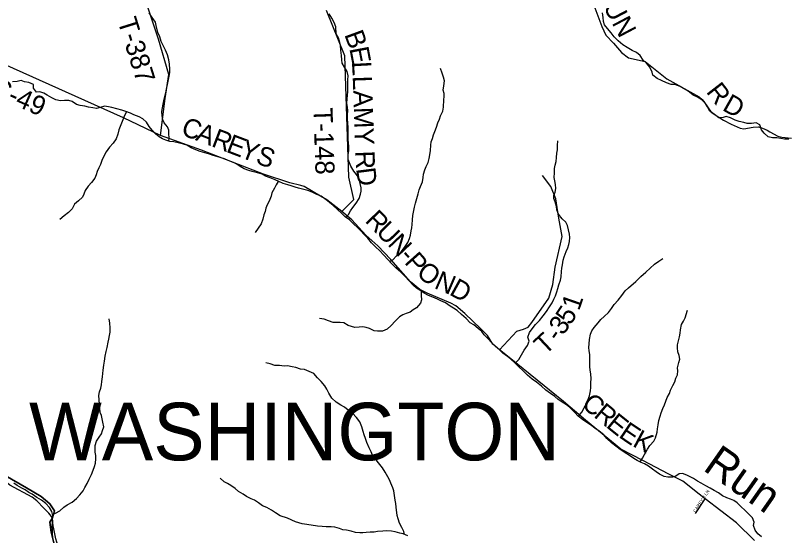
# Model space of a CAD drawing. Extents: x 1624196 to 2029251, y 146837 to 440034.
# Drawn here: x 1799187 to 1811228, y 265741 to 273872 of the extents above; entities that cross this region are included whole.
import ezdxf

# ---------------------------------------------------------------- set-up
doc = ezdxf.new("R2010")
doc.units = 0
for name, color, linetype in [('GM_X_County_Road', 7, 'Continuous'), ('GM_X_County_Road_Text', 7, 'Continuous'), ('GM_X_Minor_River', 7, 'Continuous'), ('GM_X_Minor_River_Text', 7, 'Continuous'), ('GM_X_Township', 7, 'Continuous'), ('GM_X_Township_Road', 7, 'Continuous'), ('GM_X_Township_Road_Text', 7, 'Continuous'), ('GM_X_Township_Subdivision', 7, 'Continuous'), ('GM_X_Township_Subdivision_Text', 7, 'Continuous'), ('GM_X_Township_Text', 7, 'Continuous')]:
    doc.layers.add(name, color=color, linetype=linetype)

msp = doc.modelspace()

# ---------------------------------------------------------------- linework, layer by layer
at = {"layer": 'GM_X_County_Road'}
for points in [[(1808218, 274031), (1808342, 273699), (1808404, 273563), (1808527, 273438), (1808649, 273294), (1808758, 273207), (1809022, 273150), (1809359, 272882), (1809863, 272597), (1809912, 272559), (1809937, 272527), (1810051, 272359), (1810095, 272327), (1810245, 272233), (1810364, 272171), (1810503, 272109), (1810563, 272100), (1810707, 272127), (1810790, 272129), (1810850, 272111), (1810927, 272077), (1810966, 272053), (1811094, 271982), (1811154, 271969), (1811305, 271951)], [(1810726, 265663), (1810447, 265938), (1809959, 266317), (1809862, 266391), (1809607, 266593), (1809390, 266700), (1808982, 266917), (1808639, 267094), (1808086, 267546), (1807745, 267836), (1806922, 268503), (1806743, 268646), (1806642, 268732), (1806557, 268868), (1806453, 268975), (1806202, 269214), (1806062, 269332), (1805984, 269374), (1805617, 269531), (1805504, 269585), (1805357, 269706), (1805047, 270059), (1804845, 270269), (1804661, 270436), (1804441, 270674), (1804283, 270805), (1804050, 270987), (1803949, 271048), (1803698, 271196), (1803646, 271212), (1803471, 271257), (1803060, 271390), (1802091, 271764), (1801451, 271994), (1800873, 272273), (1800121, 272608), (1798898, 273159)]]:
    msp.add_lwpolyline(points, dxfattribs=at)
at = {"layer": 'GM_X_Minor_River'}
for points in [[(1801383, 273713), (1801375, 273768), (1801321, 273840), (1801274, 273913)], [(1804189, 273695), (1804165, 273759), (1804129, 273831), (1804084, 273898)], [(1808432, 273668), (1808384, 273722), (1808368, 273776), (1808362, 273838), (1808353, 273911)], [(1801584, 271906), (1801587, 271957), (1801585, 272023), (1801580, 272077), (1801562, 272131), (1801512, 272192), (1801489, 272242), (1801477, 272300), (1801474, 272369), (1801484, 272429), (1801494, 272485), (1801505, 272535), (1801521, 272605), (1801534, 272661), (1801546, 272721), (1801560, 272790), (1801575, 272872), (1801587, 272922), (1801596, 272978), (1801596, 273034), (1801593, 273111), (1801583, 273177), (1801560, 273257), (1801532, 273328), (1801496, 273404), (1801465, 273465), (1801443, 273535), (1801412, 273607), (1801383, 273713)], [(1804347, 270713), (1804390, 270759), (1804420, 270815), (1804455, 270867), (1804509, 270937), (1804552, 271009), (1804574, 271077), (1804584, 271127), (1804585, 271179), (1804571, 271247), (1804561, 271298), (1804530, 271366), (1804472, 271437), (1804425, 271513), (1804403, 271568), (1804385, 271622), (1804382, 271692), (1804392, 271754), (1804393, 271827), (1804389, 271877), (1804384, 271939), (1804380, 272011), (1804380, 272065), (1804383, 272128), (1804379, 272184), (1804374, 272260), (1804374, 272310), (1804376, 272387), (1804371, 272439), (1804363, 272501), (1804366, 272561), (1804372, 272623), (1804376, 272678), (1804377, 272730), (1804375, 272798), (1804378, 272866), (1804382, 272928), (1804366, 272993), (1804325, 273065), (1804291, 273126), (1804286, 273176), (1804280, 273246), (1804269, 273331), (1804261, 273401), (1804251, 273451), (1804234, 273519), (1804194, 273586), (1804189, 273695)], [(1810237, 272278), (1810171, 272270), (1810101, 272321), (1810030, 272373), (1809992, 272444), (1809960, 272494), (1809903, 272551), (1809839, 272595), (1809769, 272626), (1809693, 272687), (1809620, 272731), (1809564, 272762), (1809484, 272790), (1809426, 272793), (1809352, 272817), (1809276, 272852), (1809206, 272888), (1809140, 272937), (1809129, 272987), (1809091, 273062), (1809040, 273126), (1808988, 273173), (1808942, 273243), (1808885, 273290), (1808819, 273324), (1808739, 273369), (1808671, 273413), (1808596, 273476), (1808534, 273539), (1808490, 273599), (1808432, 273668)], [(1805029, 270025), (1805082, 270052), (1805138, 270112), (1805211, 270178), (1805263, 270244), (1805316, 270322), (1805340, 270386), (1805355, 270436), (1805367, 270502), (1805375, 270552), (1805384, 270604), (1805388, 270678), (1805391, 270745), (1805407, 270823), (1805420, 270877), (1805436, 270939), (1805456, 271011), (1805473, 271081), (1805491, 271145), (1805512, 271199), (1805542, 271272), (1805555, 271336), (1805559, 271390), (1805579, 271458), (1805602, 271508), (1805630, 271572), (1805649, 271636), (1805659, 271692), (1805666, 271758), (1805672, 271845), (1805680, 271897), (1805697, 271947), (1805717, 272007), (1805734, 272057), (1805760, 272125), (1805784, 272191), (1805807, 272251), (1805825, 272301), (1805862, 272377), (1805872, 272437), (1805877, 272550), (1805883, 272602), (1805880, 272652), (1805866, 272702), (1805878, 272771), (1805885, 272847), (1805869, 272907), (1805850, 272971), (1805822, 273044)], [(1804282, 270774), (1804214, 270838), (1804150, 270899), (1804089, 270947), (1804037, 270990), (1803961, 271045), (1803893, 271075), (1803818, 271108), (1803752, 271136), (1803692, 271153), (1803608, 271173), (1803554, 271186), (1803492, 271206), (1803438, 271222), (1803368, 271245), (1803298, 271274), (1803244, 271300), (1803166, 271335), (1803093, 271359), (1803039, 271388), (1802965, 271412), (1802883, 271431), (1802831, 271447), (1802761, 271474), (1802697, 271512), (1802633, 271553), (1802564, 271585), (1802508, 271606), (1802452, 271630), (1802382, 271653), (1802330, 271669), (1802274, 271683), (1802216, 271702), (1802144, 271722), (1802074, 271745), (1802002, 271773), (1801932, 271804), (1801863, 271844), (1801811, 271861), (1801727, 271881), (1801663, 271894), (1801597, 271902), (1801537, 271921), (1801485, 271941), (1801431, 271974), (1801377, 272016), (1801320, 272077), (1801276, 272137), (1801232, 272204), (1801175, 272254), (1801117, 272289), (1801037, 272319), (1800985, 272342), (1800911, 272370), (1800847, 272391), (1800773, 272409), (1800695, 272432), (1800641, 272444), (1800579, 272453), (1800509, 272433), (1800455, 272419), (1800395, 272426), (1800327, 272436), (1800271, 272453), (1800197, 272463), (1800141, 272479), (1800075, 272524), (1800023, 272540), (1799951, 272541), (1799893, 272535), (1799819, 272552), (1799757, 272586), (1799684, 272625), (1799632, 272659), (1799566, 272676), (1799514, 272670), (1799468, 272737), (1799468, 272791), (1799397, 272825), (1799327, 272834), (1799275, 272854), (1799213, 272839), (1799144, 272831)], [(1800919, 272367), (1800891, 272306), (1800852, 272216), (1800821, 272138), (1800803, 272082), (1800787, 272016), (1800758, 271942), (1800714, 271876), (1800657, 271810), (1800605, 271740), (1800558, 271652), (1800536, 271602), (1800517, 271544), (1800491, 271488), (1800465, 271430), (1800446, 271378), (1800428, 271328), (1800375, 271258), (1800325, 271204), (1800276, 271134), (1800254, 271080), (1800236, 271030), (1800171, 270976), (1800111, 270920), (1800074, 270850), (1800014, 270790), (1799947, 270741), (1799881, 270683)], [(1811264, 271938), (1811198, 271939), (1811138, 271947), (1811074, 271956), (1811008, 271958), (1810942, 271976), (1810876, 272029), (1810838, 272083), (1810809, 272162), (1810751, 272192), (1810681, 272183), (1810613, 272183), (1810559, 272200), (1810487, 272214), (1810427, 272236), (1810355, 272273), (1810287, 272290), (1810237, 272278)], [(1806988, 268438), (1807045, 268495), (1807088, 268565), (1807130, 268641), (1807185, 268710), (1807207, 268781), (1807190, 268845), (1807216, 268915), (1807253, 268971), (1807307, 269039), (1807372, 269103), (1807426, 269175), (1807479, 269244), (1807527, 269318), (1807566, 269380), (1807596, 269434), (1807618, 269490), (1807641, 269549), (1807655, 269603), (1807672, 269659), (1807698, 269733), (1807706, 269785), (1807715, 269867), (1807719, 269923), (1807728, 269973), (1807738, 270044), (1807755, 270098), (1807785, 270182), (1807810, 270240), (1807826, 270290), (1807836, 270340), (1807843, 270398), (1807837, 270454), (1807821, 270521), (1807808, 270589), (1807780, 270639), (1807726, 270694), (1807667, 270765), (1807641, 270835), (1807634, 270887), (1807616, 270958), (1807592, 271008), (1807595, 271058), (1807615, 271108), (1807627, 271164), (1807618, 271230), (1807608, 271287), (1807599, 271339), (1807603, 271413), (1807605, 271477), (1807616, 271529), (1807630, 271586), (1807635, 271650), (1807643, 271718), (1807649, 271772), (1807652, 271840), (1807654, 271913)], [(1803291, 271277), (1803260, 271226), (1803231, 271172), (1803191, 271100), (1803179, 271048), (1803150, 270969), (1803120, 270913), (1803099, 270859), (1803085, 270807), (1803067, 270757), (1803048, 270685), (1803024, 270615), (1802977, 270545), (1802931, 270477)], [(1810517, 266189), (1810456, 266254), (1810404, 266290), (1810350, 266311), (1810296, 266329), (1810230, 266362), (1810163, 266408), (1810095, 266447), (1810033, 266481), (1809965, 266520), (1809895, 266558), (1809839, 266593), (1809774, 266635), (1809722, 266660), (1809670, 266688), (1809602, 266711), (1809550, 266707), (1809500, 266669), (1809448, 266653), (1809375, 266656), (1809315, 266666), (1809244, 266699), (1809192, 266737), (1809134, 266780), (1809074, 266824), (1809012, 266861), (1808955, 266885), (1808897, 266916), (1808845, 266946), (1808777, 266993), (1808707, 267035), (1808632, 267088), (1808564, 267137), (1808496, 267193), (1808421, 267256), (1808373, 267314), (1808301, 267373), (1808235, 267422), (1808168, 267472), (1808096, 267517), (1808044, 267557), (1807976, 267610), (1807919, 267672), (1807845, 267743), (1807791, 267784), (1807724, 267824), (1807664, 267869), (1807612, 267917), (1807542, 267962), (1807471, 268014), (1807399, 268079), (1807325, 268138), (1807258, 268188), (1807184, 268251), (1807114, 268318), (1807047, 268378), (1806985, 268441), (1806923, 268501), (1806868, 268540), (1806798, 268592), (1806738, 268649), (1806686, 268690), (1806625, 268756), (1806565, 268821), (1806507, 268881), (1806468, 268932), (1806410, 268978), (1806344, 269035), (1806290, 269069), (1806225, 269132), (1806151, 269195), (1806086, 269261), (1806026, 269296), (1805974, 269328), (1805904, 269379), (1805830, 269413), (1805778, 269438), (1805703, 269466), (1805635, 269493), (1805567, 269531), (1805515, 269566), (1805447, 269610), (1805395, 269653), (1805334, 269723), (1805270, 269792), (1805203, 269861), (1805129, 269927), (1805057, 269992), (1805000, 270059), (1804938, 270125), (1804871, 270196), (1804813, 270251), (1804747, 270319), (1804688, 270388), (1804626, 270452), (1804580, 270503), (1804531, 270553), (1804467, 270616), (1804403, 270675), (1804336, 270721), (1804282, 270774)], [(1807978, 267609), (1808031, 267668), (1808067, 267736), (1808110, 267804), (1808126, 267860), (1808149, 267928), (1808167, 268004), (1808172, 268058), (1808172, 268134), (1808176, 268193), (1808171, 268271), (1808161, 268327), (1808158, 268385), (1808156, 268446), (1808156, 268496), (1808155, 268572), (1808147, 268628), (1808142, 268682), (1808146, 268737), (1808152, 268807), (1808165, 268887), (1808187, 268939), (1808226, 268995), (1808284, 269067), (1808329, 269121), (1808379, 269167), (1808445, 269226), (1808496, 269288), (1808538, 269352), (1808597, 269420), (1808655, 269492), (1808710, 269566), (1808760, 269616), (1808873, 269715), (1808952, 269789), (1809028, 269859), (1809099, 269919), (1809167, 269981), (1809235, 270032), (1809294, 270070)], [(1805521, 269562), (1805521, 269496), (1805530, 269427), (1805510, 269373), (1805449, 269303), (1805399, 269270), (1805349, 269234), (1805288, 269210), (1805238, 269194), (1805184, 269160), (1805118, 269095), (1805053, 269025), (1804991, 268967), (1804918, 268935), (1804840, 268936), (1804790, 268942), (1804718, 268977), (1804664, 268991), (1804610, 269004), (1804554, 269000), (1804488, 268996), (1804436, 269007), (1804384, 269025), (1804313, 269064), (1804257, 269074), (1804203, 269070), (1804150, 269071), (1804073, 269097), (1804007, 269124), (1803933, 269134)], [(1808942, 266892), (1808977, 266953), (1809011, 267011), (1809058, 267091), (1809094, 267151), (1809153, 267217), (1809181, 267269), (1809208, 267357), (1809212, 267409), (1809221, 267470), (1809235, 267540), (1809252, 267608), (1809268, 267662), (1809296, 267726), (1809323, 267784), (1809341, 267842), (1809366, 267902), (1809398, 267962), (1809418, 268016), (1809453, 268088), (1809481, 268144), (1809500, 268202), (1809524, 268256), (1809528, 268315), (1809523, 268365), (1809547, 268447), (1809560, 268501), (1809552, 268557), (1809530, 268614), (1809525, 268674), (1809527, 268724), (1809538, 268784), (1809558, 268848), (1809564, 268904), (1809573, 268957), (1809589, 269039), (1809616, 269095), (1809642, 269147), (1809683, 269267)], [(1799764, 266076), (1799815, 266090), (1799883, 266129), (1799944, 266185), (1799994, 266221), (1800074, 266263), (1800143, 266322), (1800193, 266378), (1800244, 266442), (1800270, 266492), (1800308, 266554), (1800341, 266622), (1800373, 266694), (1800400, 266766), (1800422, 266820), (1800435, 266872), (1800441, 266939), (1800441, 266995), (1800434, 267047), (1800430, 267099), (1800432, 267151), (1800453, 267217), (1800493, 267277), (1800532, 267331), (1800548, 267383), (1800566, 267440), (1800553, 267512), (1800543, 267566), (1800530, 267616), (1800512, 267667), (1800506, 267733), (1800499, 267795), (1800493, 267861), (1800492, 267932), (1800502, 267986), (1800520, 268044), (1800531, 268096), (1800535, 268148), (1800546, 268222), (1800552, 268274), (1800558, 268325), (1800569, 268403), (1800579, 268469), (1800590, 268545), (1800604, 268619), (1800619, 268683), (1800633, 268762), (1800646, 268812), (1800658, 268866), (1800666, 268922), (1800669, 268988), (1800661, 269060), (1800650, 269129)], [(1805260, 265760), (1805252, 265803), (1805220, 265867), (1805183, 265935), (1805165, 266002), (1805150, 266054), (1805130, 266185), (1805125, 266241), (1805117, 266293), (1805108, 266367), (1805094, 266438), (1805082, 266488), (1805051, 266560), (1805027, 266611), (1805003, 266661), (1804962, 266730), (1804920, 266802), (1804857, 266877), (1804803, 266947), (1804763, 267000), (1804740, 267050), (1804710, 267112), (1804675, 267197), (1804655, 267261), (1804635, 267318), (1804618, 267370), (1804594, 267442), (1804563, 267519), (1804515, 267587), (1804451, 267656), (1804384, 267700), (1804324, 267749), (1804270, 267781), (1804196, 267826), (1804129, 267891), (1804083, 267969), (1804048, 268028), (1804018, 268080), (1803960, 268147), (1803905, 268209), (1803845, 268272), (1803773, 268306), (1803699, 268335), (1803639, 268343), (1803567, 268368), (1803507, 268378), (1803435, 268395), (1803385, 268391), (1803309, 268398), (1803239, 268402), (1803167, 268425), (1803095, 268441)], [(1803434, 266011), (1803322, 266051), (1803246, 266098), (1803188, 266139), (1803111, 266179), (1803043, 266208), (1802983, 266252), (1802921, 266293), (1802869, 266317), (1802797, 266352), (1802744, 266386), (1802672, 266431), (1802620, 266475), (1802550, 266522), (1802496, 266554), (1802445, 266583), (1802383, 266641)], [(1799770, 265717), (1799765, 265767), (1799765, 265835), (1799763, 265885), (1799766, 265953), (1799766, 266006), (1799769, 266056), (1799755, 266118), (1799721, 266180), (1799662, 266243), (1799594, 266294), (1799522, 266336), (1799446, 266387), (1799395, 266417), (1799341, 266456), (1799287, 266484), (1799213, 266525), (1799161, 266559)], [(1810837, 265720), (1810777, 265770), (1810737, 265827), (1810712, 265899), (1810720, 265949), (1810696, 266017), (1810639, 266078), (1810575, 266137), (1810517, 266189)], [(1805312, 265738), (1805242, 265768), (1805190, 265779), (1805114, 265799), (1805058, 265810), (1804986, 265814), (1804926, 265811), (1804840, 265803), (1804788, 265797), (1804726, 265796), (1804665, 265790), (1804613, 265784), (1804563, 265785), (1804495, 265789), (1804427, 265810), (1804355, 265824), (1804301, 265833), (1804247, 265851), (1804174, 265872), (1804117, 265878), (1804039, 265878), (1803979, 265881), (1803903, 265887), (1803735, 265912), (1803663, 265927), (1803611, 265939), (1803559, 265954), (1803434, 266011)]]:
    msp.add_lwpolyline(points, dxfattribs=at)
at = {"layer": 'GM_X_Township'}
for points in [[(1799025, 266678), (1799362, 266488), (1799591, 266354), (1799726, 266236), (1799799, 266128), (1799766, 266019), (1799724, 265951), (1799746, 265796), (1799799, 265587)], [(1799799, 265587), (1799746, 265796), (1799724, 265951), (1799766, 266019), (1799799, 266128), (1799726, 266236), (1799591, 266354), (1799362, 266488), (1799025, 266678)]]:
    msp.add_lwpolyline(points, dxfattribs=at)
at = {"layer": 'GM_X_Township_Road'}
for points in [[(1801451, 271994), (1801523, 272573), (1801581, 272946), (1801420, 273502), (1801149, 274317), (1801048, 274569), (1801012, 274761), (1800994, 274910), (1800969, 275024), (1800889, 275194), (1800715, 275501), (1800536, 275757), (1800492, 275897), (1800429, 276159), (1800345, 276425)], [(1804283, 270805), (1804470, 270993), (1804395, 271341), (1804329, 273240), (1804043, 273950)], [(1806743, 268646), (1807016, 268938), (1807121, 268970), (1807193, 269001), (1807250, 269070), (1807518, 269451), (1807576, 269666), (1807613, 269939), (1807722, 270416), (1807673, 270702), (1807627, 271004), (1807546, 271200), (1807416, 271368)], [(1799786, 265844), (1799778, 265885), (1799766, 266019), (1799708, 266090), (1799633, 266168), (1799523, 266285), (1799447, 266341), (1799099, 266528), (1798839, 266744), (1798782, 266869), (1798705, 267109), (1798640, 267243), (1798546, 267369), (1798481, 267491), (1798370, 267915), (1798222, 268311), (1798178, 268639)], [(1799971, 264592), (1799960, 264632), (1799896, 264752), (1799854, 264842), (1799839, 265045), (1799839, 265140), (1799901, 265294), (1799922, 265377), (1799907, 265444), (1799864, 265535), (1799816, 265688), (1799786, 265844)]]:
    msp.add_lwpolyline(points, dxfattribs=at)
at = {"layer": 'GM_X_Township_Subdivision'}
msp.add_lwpolyline([(1809808, 266086), (1809959, 266317)], dxfattribs=at)

# ---------------------------------------------------------------- texts
at = {"layer": 'GM_X_County_Road_Text'}
for s, rotation, p in [('RUN', 297.8026, (1808224, 274269)), ('C-49', 336.0372, (1798783, 272641)), ('R', 307.807, (1809962, 272676)), ('D', 330.5107, (1810209, 272398)), ('C', 339.0767, (1801756, 272013)), ('A', 339.0743, (1801986, 271925)), ('R', 339.0777, (1802233, 271831)), ('E', 339.0748, (1802463, 271743)), ('Y', 339.0855, (1802673, 271663)), ('S', 339.5388, (1802922, 271568)), ('R', 314.2466, (1804632, 270653)), ('U', 314.2234, (1804803, 270476)), ('N', 313.5149, (1804987, 270288)), ('-', 312.0154, (1805167, 270098)), ('P', 311.7259, (1805249, 270007)), ('O', 323.2106, (1805432, 269811)), ('N', 336.8563, (1805711, 269614)), ('D', 331.1439, (1805947, 269514)), ('C', 319.1185, (1808010, 267771)), ('R', 320.5166, (1808203, 267605)), ('E', 321.019, (1808395, 267446)), ('E', 325.94, (1808592, 267288)), ('K', 332.0678, (1808808, 267145))]:
    msp.add_text(s, height=300, rotation=rotation, dxfattribs=at).set_placement(p)
at = {"layer": 'GM_X_Minor_River_Text'}
msp.add_text('Run', height=500, rotation=325.001, dxfattribs=at).set_placement((1809905, 266774))
at = {"layer": 'GM_X_Township_Road_Text'}
for s, rotation, p in [('T-387', 287.3048, (1800779, 273788)), ('B', 290.1045, (1804319, 273575)), ('E', 280.7817, (1804400, 273356)), ('L', 273.1215, (1804441, 273146)), ('L', 271.9889, (1804453, 272923)), ('A', 271.9857, (1804461, 272699)), ('T-148', 271.9653, (1803838, 272426)), ('M', 271.9879, (1804470, 272435)), ('Y', 271.9883, (1804481, 272110)), ('R', 272.201, (1804494, 271752)), ('D', 277.2215, (1804506, 271477)), ('1', 70.9493, (1807987, 269244)), ('5', 56.3361, (1807848, 269016)), ('3', 54.9184, (1807737, 268858)), ('T', 43.1602, (1807458, 268552)), ('-', 55.2351, (1807667, 268757))]:
    msp.add_text(s, height=300, rotation=rotation, dxfattribs=at).set_placement(p)
at = {"layer": 'GM_X_Township_Subdivision_Text'}
msp.add_text("CAREY'S LN", height=50, rotation=56.9156, dxfattribs=at).set_placement((1809807, 266096))
at = {"layer": 'GM_X_Township_Text'}
msp.add_text('WASHINGTON', height=900, rotation=0, dxfattribs=at).set_placement((1799400, 266917))

doc.saveas('drawing.dxf')
